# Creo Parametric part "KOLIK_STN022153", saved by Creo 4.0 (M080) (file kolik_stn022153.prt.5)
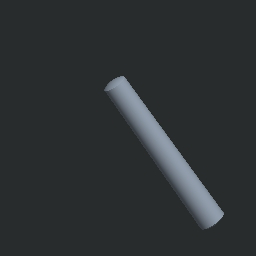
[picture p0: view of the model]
Units: millimeter Kilogram Sec (mmKs); MM, KILOGRAM, SECS
Materials in the file: OCEL_N

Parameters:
  MFG_WP_MATERIAL = "OCEL"
  NAZOV = "KOLIK_STN022153"
  NORMA = "STN 02 2153"
  PTC_MATERIAL_NAME = "OCEL_N"

Other parameters: HMOTNOST, HUSTOTA, D2, D3

Created from: C022153.PRT

Layers: 1, 2, 3, 4, 5, 6, 7, 8, 9, 10, 11, 12, 13, 14, 15, 16, 17, 18, 19, 20, 21, 22, 23, 24, 25, 26, 27, 28, 29, 30, 31, 32

Family table entries: GENERIC, KOLIK_0_6, KOLIK_STN022153, value(d_val), value(i_val), KOLIK_0_8, KOLIK_STN022153, KOLIK_1, KOLIK_STN022153, KOLIK_1_2, KOLIK_STN022153, KOLIK_1_5, KOLIK_STN022153, KOLIK_2, KOLIK_STN022153, KOLIK_2_5, KOLIK_STN022153, KOLIK_3, KOLIK_STN022153, KOLIK_4, KOLIK_STN022153, KOLIK_5, KOLIK_STN022153, KOLIK_6, KOLIK_STN022153, KOLIK_8, KOLIK_STN022153, !/ , KOLIK_10, KOLIK_STN022153, !/$, KOLIK_12, KOLIK_STN022153, !/(, KOLIK_16, KOLIK_STN022153, !/0, KOLIK_20, KOLIK_STN022153, !/4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

Surfaces: 4 torus, 2 cone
